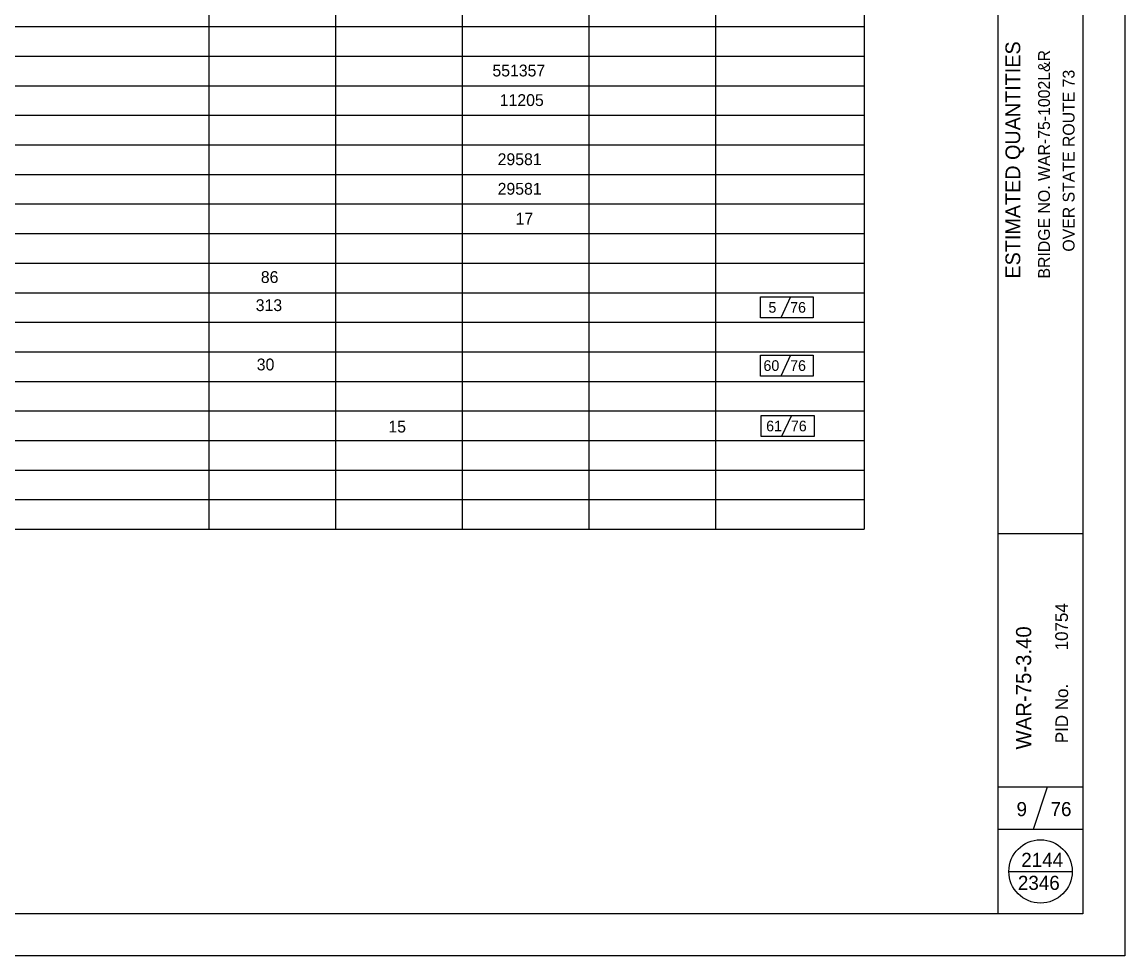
# Model space of a CAD drawing. Extents: x 0 to 34, y 0 to 22.
# Drawn here: x 20.94 to 34, y 0 to 11.06 of the extents above; entities that cross this region are included whole.
import ezdxf

# ---------------------------------------------------------------- set-up
doc = ezdxf.new("R2010")
doc.units = 0
for name, color, linetype in [('BR_P_Gen_Text', 7, 'Continuous'), ('BR_P_Sub_Text', 7, 'Continuous'), ('SH_Border', 7, 'Continuous'), ('SH_Cut_Line', 7, 'Continuous'), ('SH_Data', 7, 'Continuous'), ('SH_Text', 7, 'Continuous')]:
    doc.layers.add(name, color=color, linetype=linetype)

msp = doc.modelspace()

# ---------------------------------------------------------------- linework, layer by layer
at = {"layer": 'BR_P_Gen_Text'}
for p, q in [((30.04, 7.803), (29.925, 7.553)), ((30.04, 7.114), (29.925, 6.864)), ((30.049, 6.399), (29.933, 6.149))]:
    msp.add_line(p, q, dxfattribs=at)
for points in [[(29.683, 7.803), (30.309, 7.803), (30.309, 7.553), (29.683, 7.553)], [(29.683, 7.803), (30.309, 7.803), (30.309, 7.553), (29.683, 7.553)], [(29.683, 7.114), (30.309, 7.114), (30.309, 6.864), (29.683, 6.864)], [(29.683, 7.114), (30.309, 7.114), (30.309, 6.864), (29.683, 6.864)], [(29.692, 6.399), (30.318, 6.399), (30.318, 6.149), (29.692, 6.149)], [(29.692, 6.399), (30.318, 6.399), (30.318, 6.149), (29.692, 6.149)]]:
    msp.add_lwpolyline(points, close=True, dxfattribs=at)
at = {"layer": 'SH_Border'}
for p, q in [((32.5, 0.5), (32.5, 21.5)), ((32.5, 0.5), (32.5, 21.5)), ((32.5, 0.5), (32.5, 21.5)), ((32.5, 5), (33.5, 5)), ((32.5, 5), (33.5, 5)), ((32.5, 5), (33.5, 5)), ((32.5, 2), (33.5, 2)), ((32.917, 1.5), (33.083, 2)), ((32.5, 1.5), (33.5, 1.5))]:
    msp.add_line(p, q, dxfattribs=at)
msp.add_lwpolyline([(2, 21.5), (33.5, 21.5), (33.5, 0.5), (2, 0.5)], close=True, dxfattribs=at)
at = {"layer": 'SH_Cut_Line'}
msp.add_lwpolyline([(0, 22), (34, 22), (34, 0), (0, 0)], close=True, dxfattribs=at)
at = {"layer": 'SH_Data'}
msp.add_line((32.625, 1), (33.375, 1), dxfattribs=at)
msp.add_line((32.625, 1), (33.375, 1), dxfattribs=at)
msp.add_line((32.625, 1), (33.375, 1), dxfattribs=at)
msp.add_circle((33, 1), 0.375, dxfattribs=at)
at = {"layer": 'SH_Text'}
for p, q in [((30.91, 19.31), (30.91, 5.052)), ((23.15, 18.352), (23.15, 5.052)), ((24.65, 18.352), (24.65, 5.052)), ((26.15, 18.352), (26.15, 5.052)), ((27.65, 18.352), (27.65, 5.052)), ((29.15, 18.352), (29.15, 5.052)), ((3.59, 11.002), (30.91, 11.002)), ((3.59, 10.652), (30.91, 10.652)), ((3.59, 10.302), (30.91, 10.302)), ((3.59, 9.952), (30.91, 9.952)), ((3.59, 9.602), (30.91, 9.602)), ((3.59, 9.252), (30.91, 9.252)), ((3.59, 8.902), (30.91, 8.902)), ((3.59, 8.552), (30.91, 8.552)), ((3.59, 8.202), (30.91, 8.202)), ((3.59, 7.852), (30.91, 7.852)), ((3.59, 7.502), (30.91, 7.502)), ((3.59, 7.152), (30.91, 7.152)), ((3.59, 6.802), (30.91, 6.802)), ((3.59, 6.452), (30.91, 6.452)), ((3.59, 6.102), (30.91, 6.102)), ((3.59, 5.752), (30.91, 5.752)), ((3.59, 5.402), (30.91, 5.402)), ((3.59, 5.052), (30.91, 5.052))]:
    msp.add_line(p, q, dxfattribs=at)

# ---------------------------------------------------------------- texts
at = {"layer": 'BR_P_Gen_Text'}
for s, p in [(' 5', (29.731, 7.615)), ('76', (30.035, 7.615)), ('60', (29.719, 6.926)), ('76', (30.035, 6.926)), ('61', (29.751, 6.211)), ('76', (30.044, 6.211))]:
    msp.add_text(s, height=0.1259, dxfattribs=at).set_placement(p)
at = {"layer": 'BR_P_Sub_Text'}
msp.add_text('WAR-75-3.40', height=0.18, rotation=90, dxfattribs=at).set_placement((32.89, 2.444))
at = {"layer": 'SH_Data'}
for s, height, p in [('ESTIMATED QUANTITIES', 0.175, (32.76, 8.019)), ('BRIDGE NO. WAR-75-1002L&R', 0.14, (33.112, 8.02)), ('OVER STATE ROUTE 73', 0.14, (33.403, 8.338)), ('10754', 0.15, (33.325, 3.618)), ('PID No.', 0.15, (33.327, 2.519))]:
    msp.add_text(s, height=height, rotation=90, dxfattribs=at).set_placement(p)
for s, height, p in [('9', 0.167, (32.716, 1.655)), ('76', 0.1666, (33.119, 1.655)), ('2144', 0.1666, (32.772, 1.054)), ('2346', 0.1666, (32.732, 0.782))]:
    msp.add_text(s, height=height, dxfattribs=at).set_placement(p)
at = {"layer": 'SH_Text'}
for s, p in [('551357', (26.509, 10.412)), ('11205', (26.596, 10.062)), ('29581', (26.571, 9.362)), ('29581', (26.571, 9.012)), ('17', (26.783, 8.659)), ('86', (23.766, 7.967)), ('313', (23.706, 7.634)), ('30', (23.718, 6.932)), ('15', (25.277, 6.197))]:
    msp.add_text(s, height=0.14, dxfattribs=at).set_placement(p)

doc.saveas('drawing.dxf')
